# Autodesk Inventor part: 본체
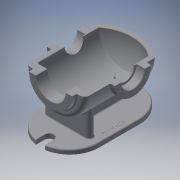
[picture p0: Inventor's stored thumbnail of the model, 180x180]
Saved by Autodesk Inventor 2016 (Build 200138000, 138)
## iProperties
Created: 2016-02
Part Number: 본체
Material: 알루미늄 6061
Document SubType Name: Modeling
Designer: mduedu
Density: 2.71 g/cm^3
Appearance: 기본값
Mass: 2164.68 g
Surface Area: 1516.76 cm^2
Volume: 798.776 cm^3
Author: mduedu
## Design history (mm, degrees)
sketch "스케치2"
  geometry: L1 (0, 90)-(0, -90); L2 (65, -65.993)-(65, 90); L3 (65, 90)-(0, 90); A1 r 100 centre (0, 10) between (0, -90) and (65, -65.993); 2 further points
  constraints: 6 end point, 2 point on circle, 1 centre point, 1 coincident, 1 horizontal, 1 midpoint, 1 parallel, 1 point on line, 1 vertical
  dimensions: "d3" = 180 distance of L1.start L1.end; "d5" = 130 diameter of L2 L1; "d6" = 100 radius of A1
revolve "회전1" sketch "스케치2" stored, may be unused: angle "d7" = 90 deg
sketch "스케치3"
  geometry: C1 r 47.5 at (0, 0); 1 further point
  constraints: 1 centre point, 1 coincident
  dimensions: "d8" = 95 diameter of C1
extrude "돌출2" join sketch "스케치3" distance "d10" = 10; taper "d11" = 0 deg
sketch "스케치5"
  geometry: L1 (47.5, 100)-(47.5, 90) reference; L2 (47.5, 90)-(65, 90) reference; L3 (65, 90)-(65, -65.993) reference; L4 (-65, -65.993)-(-65, 90) reference; L5 (-65, 90)-(-47.5, 90) reference; L6 (-47.5, 90)-(-47.5, 100) reference; L7 (-47.5, 100)-(47.5, 100) reference; L8 (55, 75)-(55, -61.239); L9 (0, 75)-(55, 75); L10 (0, 75)-(0, -80); A1 r 100 centre (0, 10) between (-65, -65.993) and (0, -90) reference; A2 r 100 centre (0, 10) between (0, -90) and (65, -65.993) reference; A3 r 90 centre (0, 10) between (0, -80) and (55, -61.239); 1 further point
  constraints: 6 end point, 2 point on circle, 1 centre point, 1 parallel, 1 perpendicular, 1 point on line, 1 vertical
  dimensions: "d13" = 10 distance between parallel lines of L3 L8; "d14" = 10 radial gap between concentric circles of A3 A1; "d15" = 15 distance between parallel lines of L9 L2
revolve "회전2" sketch "스케치5" stored, may be unused: angle "d16" = 90 deg
hole "구멍1" diameter "d19" = 65; stored, may be unused: countersink angle "d23" = 90 deg, drill point angle "d25" = 118 deg; dims "d17" = 10, "d18" = 10, "d20" = 6, "d21" = 4, "d22" = 2, "d24" = 8
node "작업 평면1"
sketch "스케치6"
  geometry: L1 (47.5, 100)-(-47.5, 100) reference; C1 r 40 at (0, -7); 1 further point
  constraints: 1 centre point, 1 vertical alignment
  dimensions: "d27" = 80 diameter of C1; "d29" = 107 distance from line of C1.centre L1
extrude "돌출3" join sketch "스케치6" stored distance "d30" = 10; taper "d31" = 0 deg
hole "구멍2" diameter "d34" = 42; stored, may be unused: countersink angle "d38" = 90 deg, drill point angle "d40" = 118 deg; dims "d32" = 10, "d33" = 10, "d35" = 6, "d36" = 52, "d37" = 18, "d39" = 8
sketch "스케치7" dims "d41" = 65
  geometry: C1 r 40 at (0, 0) reference; 3 further points
  constraints: 2 vertical alignment, 1 coincident, 2 other
hole "구멍3" sketch "스케치7" at (0, 32.5) diameter "d43" = 3.242; stored, may be unused: countersink angle "d47" = 90 deg, drill point angle "d49" = 118 deg; dims "d44" = 11, "d45" = 13, "d46" = 18, "d48" = 13
sketch "스케치8" dims "d53" = 80
  geometry: 3 further points
  constraints: 2 vertical alignment, 1 coincident, 2 other
hole "구멍4" sketch "스케치8" at (0, -40) diameter "d56" = 3.242; stored, may be unused: countersink angle "d60" = 90 deg, drill point angle "d62" = 118 deg; dims "d57" = 11, "d58" = 13, "d59" = 18, "d61" = 13
fillet "모깎기1" dims "d66" = 10
fillet "모깎기2" dims "d67" = 3
fillet "모깎기3" dims "d68" = 0.3
chamfer "모따기1" distance "d69" = 1; stored, may be unused: second distance "d70" = 2, angle "d71" = 45 deg
node "작업 평면5"
sketch "스케치10"
  geometry: L1 (-50, 66)-(50, 66); L2 (50, 66)-(50, 50); L3 (50, 50)-(-50, 50); L4 (-50, 50)-(-50, 66); 2 further points
  constraints: 8 end point, 2 horizontal, 2 vertical, 1 midpoint, 1 vertical alignment
  dimensions: "d177" = 50 distance from line of L3 point (0, 0); "d178" = 100 distance of L1.start L1.end; "d179" = 16 distance of L3.end L1.start
extrude "돌출5" join sketch "스케치10" stored distance "d84" = 10; taper "d85" = 0 deg
sketch "스케치21" dims "d180" = 220, "d182" = 130
  geometry: L1 (65, 58)-(-65, 58); L2 (-65, 58)-(-65, -32); L3 (-65, -32)-(65, -32); L4 (65, -32)-(65, 58); L5 (50, 50)-(50, 66) reference; 4 further points
  constraints: 8 end point, 3 horizontal alignment, 3 midpoint, 2 parallel, 1 horizontal, 1 perpendicular, 1 vertical alignment, 4 other
extrude "돌출13" join sketch "스케치21" distance "d183" = 10; taper "d184" = 0 deg
sketch "스케치11"
  geometry: L1 (-65, 80)-(-65, -61.239) reference; L2 (-100, -97)-(-100, -32) reference; L3 (-65, -42.793)-(-100, -63); L4 (-100, -97)-(-110, -97) reference; 1 further point
  constraints: 2 end point, 2 point on line
  dimensions: "d185" = 34 distance from line of L3.end L4; "d186" = 120 deg angle of L2 L3
feature "리브1" sketch "스케치11" dims "d88" = 1, "d89" = 16, "d90" = 0, "d91" = 0, "d92" = 1, "d93" = 1
fillet "모깎기12"
fillet "모깎기13"
fillet "모깎기16" dims "d167" = 3
fillet "모깎기18"
fillet "모깎기17" dims "d168" = 3
fillet "모깎기19" dims "d187" = 3
node "작업 평면6"
sketch "스케치19"
  geometry: L1 (75, -47)-(75, 33) reference; L2 (-75, -47)-(-75, 33) reference; L3 (75, -7)-(-75, -7); C1 r 22.5 at (0, -7); 1 further point
  constraints: 3 midpoint, 2 end point, 1 centre point
  dimensions: "d149" = 45 diameter of C1
extrude "돌출11" join sketch "스케치19" stored distance "d150" = 10; taper "d151" = 0 deg
hole "구멍6" diameter "d154" = 33.376; stored, may be unused: countersink angle "d158" = 90 deg, drill point angle "d160" = 118 deg; dims "d155" = 6, "d156" = 4, "d157" = 2, "d159" = 8, "d190" = 10, "d191" = 10
fillet "모깎기11" dims "d161" = 3
chamfer "모따기3" distance "d164" = 1; stored, may be unused: second distance "d165" = 2, angle "d166" = 45 deg
node "작업 평면9"
  node "작업 평면8"
sketch "스케치22" dims "d189" = 20
  geometry: L1 (-10, -123)-(10, -123); L2 (10, -123)-(10, -103); L3 (10, -103)-(-10, -103); L4 (-10, -103)-(-10, -123); A1 r 65 centre (0, -58) between (-65, -58) and (65, -58) reference; 2 further points
  constraints: 8 end point, 2 parallel, 1 horizontal, 1 horizontal alignment, 1 midpoint, 1 perpendicular, 1 tangent, 1 vertical alignment, 2 other
  dimensions: "d193" = 30 dimension on L1
extrude "돌출14" cut sketch "스케치22" stored distance "d194" = 10; taper "d195" = 0 deg
fillet "모깎기21" dims "d196" = 3
feature "분할1"
sketch "스케치23"
  geometry: L1 (-65, 32)-(-65, -58) reference; L2 (65, -58)-(65, 32) reference; L3 (-65, -13)-(65, -13); 2 further points
  constraints: 2 end point, 2 midpoint, 1 point on line, 1 other
  dimensions: "d197" = 12 distance from line of point (53, -13) L2
feature "엠보싱2" sketch "스케치23" dims "d8" = 95, "d198" = 0.5, "d199" = 0
node "솔리드2"
pattern_circular "원형 패턴1" dims angle "d51" = 360 deg
mirror "대칭1"
pattern_circular "원형 패턴2" dims angle "d64" = 360 deg
mirror "대칭3"
node "절단 모서리 투영1"
other parameters: "d26" = 75, "d136" = 175
